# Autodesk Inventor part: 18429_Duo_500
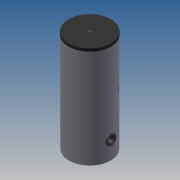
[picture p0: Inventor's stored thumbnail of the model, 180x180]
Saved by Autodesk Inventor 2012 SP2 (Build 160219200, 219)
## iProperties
allow_slope_adjustment: 0 ul
connection_type: 13 ul
flow_configuration2: 1 ul
flow_direction: 2 ul
loss_method: 0 ul
radius: 15,375 mm
radius: 12,250 mm
description: 0:0:18429_Duo_500
manufacturer: 0:0:Flamco Group
model: 0:0:Duo 500
url: 0:0:www.flamcogroup.com
Created: 2014-05
Part Number: 18429_Duo_500
Material: Default
Document SubType Name: Modeling
Designer: michel
Density: 1 g/cm^3
radius: 22,625 mm
radius: 19,625 mm
Author: michel
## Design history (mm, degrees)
sketch "Sketch1"
  geometry: C1 r 375 at (0, 0); 1 further point
  constraints: 1 centre point, 1 coincident
  dimensions: "d0" = 750 diameter of C1
extrude "Extrusion1" new body sketch "Sketch1" distance "d1" = 1830; taper "d2" = 0 deg
sketch "Sketch2"
  geometry: L1 (-375, 1830)-(375, 1830) reference; L2 (-375, 0)-(375, 0) reference; L3 (375, 0)-(375, 1830) reference; L4 (375, 1830)-(380, 1830); L5 (380, 1830)-(380, 1780); L6 (380, 1780)-(375, 1780); L7 (375, 1780)-(375, 1830); L8 (0, -326)-(0, 1956) reference; 1 further point
  constraints: 8 end point, 2 parallel, 1 horizontal, 1 perpendicular
  dimensions: "d3" = 5 distance of L5.end L6.end; "d4" = 50 distance of L4.end L5.end
revolve "Revolution1" sketch "Sketch2" stored, may be unused: angle "d5" = 90 deg
workplane "Work Plane1"
workplane "Work Plane2"
workplane "Work Plane3"
workplane "Work Plane4"
workplane "Work Plane5"
workplane "Work Plane6"
sketch "Sketch3"
  geometry: L1 (525, 1670)-(-525, 1670) reference; L2 (526.398, 990)-(-525.233, 990) reference; L3 (526.398, 890)-(-525.233, 890) reference; L4 (525, 330)-(-525, 330) reference; L5 (525, 70)-(-525, 70) reference; L6 (375, 0)-(375, 1780) reference; L7 (375, 1670)-(335, 1670); L8 (335, 1670)-(335, 1686.625); L9 (335, 1686.625)-(375, 1686.625); L10 (375, 1686.625)-(375, 1670); L11 (375, 990)-(335, 990); L12 (335, 990)-(335, 1003.22); L13 (335, 1003.22)-(375, 1003.22); L14 (375, 1003.22)-(375, 990); L15 (335, 1654.625)-(335, 1653.375); L16 (335, 1653.375)-(376, 1653.375); L17 (376, 1653.375)-(376, 1654.625); L18 (376, 1654.625)-(335, 1654.625); L19 (335, 890)-(335, 906.625); L20 (375, 890)-(335, 890); L21 (335, 906.625)-(375, 906.625); L22 (375, 906.625)-(375, 890); L23 (335, 874.625)-(335, 873.375); L24 (335, 873.375)-(376, 873.375); L25 (376, 873.375)-(376, 874.625); L26 (376, 874.625)-(335, 874.625); L27 (335.165, 346.625)-(375.165, 346.625); L28 (335.165, 330)-(335.165, 346.625); L29 (375.165, 330)-(335.165, 330); L30 (375.165, 346.625)-(375.165, 330); L31 (376.165, 314.625)-(335.165, 314.625); L32 (335.165, 314.625)-(335.165, 313.375); L33 (335.165, 313.375)-(376.165, 313.375); L34 (376.165, 313.375)-(376.165, 314.625); L35 (335, 86.625)-(375, 86.625); L36 (335, 70)-(335, 86.625); L37 (375, 70)-(335, 70); L38 (375, 86.625)-(375, 70); L39 (376, 54.625)-(335, 54.625); L40 (335, 54.625)-(335, 53.375); L41 (335, 53.375)-(376, 53.375); L42 (376, 53.375)-(376, 54.625); L43 (335, 976.78)-(375, 976.78); L44 (335, 977.75)-(335, 976.78); L45 (375, 976.78)-(376, 976.78); L46 (376, 976.78)-(376, 977.75); L47 (376, 977.75)-(335, 977.75); 2 further points
  constraints: 82 end point, 12 parallel, 6 horizontal, 6 perpendicular, 2 point on line
  dimensions: "d19" = 40 distance of L8.end L9.end; "d21" = 40 distance of L12.end L13.end; "d68" = 15.375 distance between parallel lines of L1 L18; "d70" = 16.625 distance between parallel lines of L1 L9; "d73" = 40 distance of L19.end L21.end; "d74" = 40 distance of L27.start L27.end; "d75" = 40 distance of L35.start L35.end; "d76" = 16.625 distance between parallel lines of L3 L21; "d77" = 1.25 distance between parallel lines of L26 L24; "d78" = 15.375 distance between parallel lines of L3 L26; "d79" = 16.625 distance between parallel lines of L4 L27; "d80" = 1.25 distance between parallel lines of L31 L33; "d81" = 15.375 distance between parallel lines of L4 L31; "d82" = 16.625 distance between parallel lines of L5 L35; "d83" = 1.25 distance between parallel lines of L39 L41; "d84" = 15.375 distance between parallel lines of L5 L39; "d85" = 13.22 distance between parallel lines of L2 L13; "d90" = 0.97 distance between parallel lines of L47 L43; "d91" = 12.25 distance between parallel lines of L2 L47
revolve "Revolution2" stored, may be unused: angle "d23" = 90 deg
sketch "Sketch5"
  geometry: L1 (-375, 0)-(-375, 1780) reference; L2 (-375, 0)-(-375, 327); L3 (-249, 327)-(-623, 327); L4 (-375, 327)-(-387.5, 327); L5 (-387.5, 327)-(-387.5, 417); L6 (-387.5, 417)-(-375, 417); L7 (-375, 417)-(-375, 327); 1 further point
  constraints: 12 end point, 2 parallel, 2 perpendicular, 1 horizontal, 1 point on line
  dimensions: "d35" = 327 distance of L1.start L2.end; "d36" = 12.5 distance of L5.end L6.end; "d37" = 90 distance of L4.end L5.end
revolve "Revolution7" sketch "Sketch5" stored, may be unused: angle "d38" = 90 deg
sketch "Sketch6"
  geometry: C1 r 62.5 at (0, 0); A1 r 90 centre (0, 0) between (90, 0) and (-90, 0) reference; 1 further point
  constraints: 1 centre point, 1 coincident
  dimensions: "d39" = 125 diameter of C1
extrude "Extrusion3" join sketch "Sketch6" stored distance "d40" = 40; taper "d41" = 0 deg
sketch "Sketch7"
  geometry: C1 r 90 at (0, 0) reference; C2 r 55 at (0, 0); 1 further point
  constraints: 1 centre point, 1 coincident
  dimensions: "d42" = 110 diameter of C2
extrude "Extrusion4" cut sketch "Sketch7" distance "d43" = 80; taper "d44" = 0 deg
sketch "Sketch8"
  geometry: C1 r 380 at (0, 0) reference; C2 r 20.955 at (0, 0)
  constraints: 1 centre point, 1 coincident
  dimensions: "d45" = 41.91 diameter of C2
extrude "Extrusion5" join sketch "Sketch8" distance "d46" = 2; taper "d47" = 0 deg
sketch "Sketch9"
  geometry: C1 r 20.955 at (0, 0) reference; C2 r 19.625 at (0, 0)
  constraints: 1 centre point, 1 coincident
  dimensions: "d48" = 39.25 diameter of C2
extrude "Extrusion6" cut sketch "Sketch9" distance "d49" = 40; taper "d50" = 0 deg
workplane "Work Plane8"
sketch "Sketch10"
  geometry: L1 (0, 375)-(1780, 375) reference; L2 (990, -731.182)-(990, 731.182) reference; L3 (990, 375)-(1013.9, 375); L4 (1013.9, 375)-(1013.9, 335); L5 (1013.9, 335)-(990, 335); L6 (990, 335)-(990, 375); 1 further point
  constraints: 8 end point, 2 parallel, 2 point on line, 1 horizontal, 1 perpendicular
  dimensions: "d52" = 23.9 distance of L4.end L5.end; "d53" = 40 distance of L3.end L4.end
revolve "Revolution8" sketch "Sketch10" stored, may be unused: angle "d54" = 90 deg
sketch "Sketch11"
  geometry: C1 r 22.625 at (0, 0); A1 r 23.9 centre (0, 0) between (23.9, 0) and (-23.9, 0) reference; 1 further point
  constraints: 1 centre point, 1 coincident
  dimensions: "d55" = 45.25 diameter of C1
extrude "Extrusion7" cut sketch "Sketch11" distance "d56" = 40; taper "d57" = 0 deg
sketch "Sketch12"
  geometry: C1 r 22.625 at (0, 0) reference; A1 r 23.9 centre (0, 0) between (-23.9, 0) and (23.9, 0) reference; A2 r 23.9 centre (0, 0) between (23.9, 0) and (-23.9, 0) reference; 1 further point
extrude "Extrusion8" join sketch "Sketch12" distance "d58" = 1; taper "d59" = 0 deg
revolve "Revolution9" stored, may be unused: angle "d69" = 90 deg
revolve "Revolution10" stored, may be unused: angle "d92" = 90 deg
revolve "Revolution11" stored, may be unused: angle "d93" = 90 deg
revolve "Revolution12" stored, may be unused: angle "d94" = 90 deg
revolve "Revolution13" stored, may be unused: angle "d95" = 90 deg
revolve "Revolution14" stored, may be unused: angle "d96" = 90 deg
revolve "Revolution15" stored, may be unused: angle "d97" = 90 deg
revolve "Revolution16" stored, may be unused: angle "d98" = 90 deg
revolve "Revolution17" stored, may be unused: angle "d99" = 90 deg
body "Solid1"
node "Projected Loop1"
other parameters: "d12" = 0, "d51" = 35 deg
